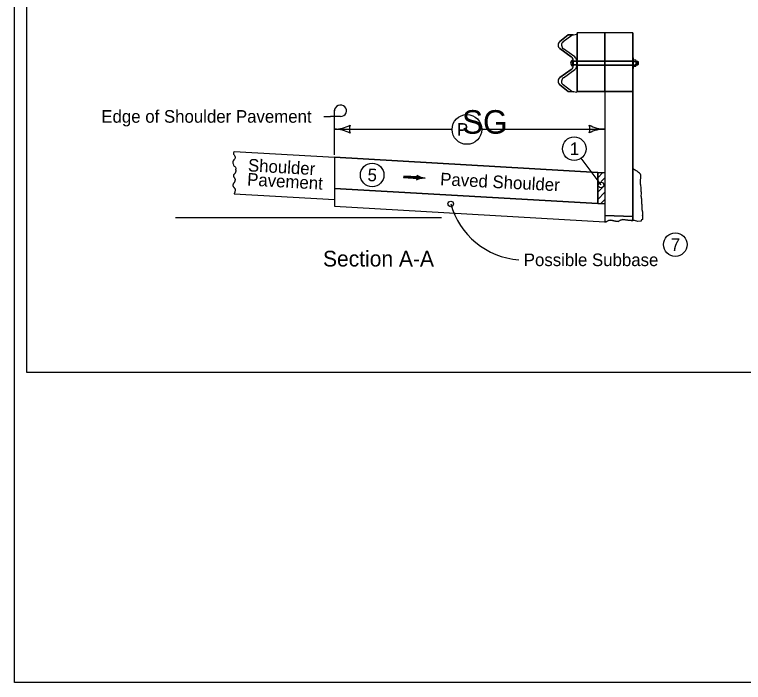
# Model space of a CAD drawing. Extents: x 9538 to 81668, y 7600 to 11751.
# Drawn here: x 17333 to 18260, y 7924 to 8774 of the extents above; entities that cross this region are included whole.
import ezdxf

# ---------------------------------------------------------------- set-up
doc = ezdxf.new("R2010")
doc.units = 0
for name, color, linetype in [('Default', 7, 'Continuous'), ('DsnShtMinorGrid13', 7, 'Continuous'), ('DsnShtMinorGrid14', 7, 'Continuous'), ('dsnStdCells', 7, 'Continuous'), ('dsnStdDimension', 7, 'Continuous'), ('dsnStdNameDate', 7, 'Continuous'), ('dsnStdNote', 7, 'Continuous'), ('dsnStdShading', 7, 'Continuous'), ('dsnStdTable', 7, 'Continuous')]:
    doc.layers.add(name, color=color, linetype=linetype)

msp = doc.modelspace()

# ---------------------------------------------------------------- linework, layer by layer
at = {"layer": 'Default'}
msp.add_lwpolyline([(17332.53, 9944.02), (20467.54, 9944.02), (20467.54, 7924.02), (17332.53, 7924.02)], close=True, dxfattribs=at)
at = {"layer": 'DsnShtMinorGrid13'}
for centre, radius in [((18044.8, 8603.28), 15), ((17787.59, 8569.91), 15), ((18078.92, 8557.17), 3.58), ((18173.39, 8481.26), 15)]:
    msp.add_circle(centre, radius, dxfattribs=at)
at = {"layer": 'DsnShtMinorGrid14'}
msp.add_circle((17887.63, 8533.07), 3.54, dxfattribs=at)
at = {"layer": 'dsnStdCells'}
for p, q in [((18026.57, 8730.73), (18041.08, 8720.31)), ((18041.08, 8704.24), (18026.57, 8693.82))]:
    msp.add_line(p, q, dxfattribs=at)
for points in [[(18030.82, 8739.63), (18030.8, 8739.62), (18041.58, 8748.02), (18043.47, 8748.36), (18037.14, 8748.24), (18026.37, 8739.85)], [(18083.86, 8714.93), (18083.86, 8750.61), (18048.31, 8750.61), (18048.31, 8714.93), (18048.31, 8714.93), (18083.86, 8714.93)], [(18119.41, 8714.93), (18119.41, 8718.93), (18119.41, 8750.61), (18083.86, 8750.61), (18083.86, 8714.93), (18119.41, 8714.93)], [(18045.52, 8720.09), (18045.55, 8720.07), (18030.98, 8730.53), (18031.01, 8730.51)], [(18043.47, 8715.68), (18043.47, 8714.6), (18047.92, 8714.6), (18047.92, 8715.46), (18047.92, 8715.46)], [(18047.92, 8708.65), (18047.92, 8708.65), (18047.92, 8709.93), (18043.47, 8709.93), (18043.47, 8708.87), (18043.47, 8709.93), (18043.47, 8709.93), (18043.47, 8708.87)], [(18048.31, 8714.6), (18048.31, 8709.93), (18048.32, 8709.93), (18083.86, 8709.93), (18083.86, 8714.6), (18048.31, 8714.6), (18048.31, 8714.6)], [(18119.41, 8709.93), (18119.41, 8714.6), (18083.86, 8714.6), (18083.86, 8709.93), (18119.41, 8709.93)], [(18031.01, 8693.6), (18030.98, 8693.58), (18045.55, 8704.04), (18045.52, 8704.02)], [(18048.31, 8709.6), (18048.31, 8675.96), (18083.86, 8675.96), (18083.86, 8709.6), (18048.31, 8709.6)], [(18119.41, 8675.96), (18119.41, 8705.6), (18119.41, 8709.6), (18083.86, 8709.6), (18083.86, 8675.96), (18119.41, 8675.96)], [(18026.37, 8684.7), (18037.14, 8676.31), (18044.24, 8675.62), (18041.58, 8676.09), (18030.8, 8684.5), (18030.82, 8684.48)], [(18119.41, 8517.01), (18119.41, 8675.96), (18083.86, 8675.96), (18083.86, 8572.99), (18083.86, 8566.3), (18083.86, 8566.3), (18083.86, 8566.3), (18083.86, 8557.07), (18083.86, 8557.07), (18083.86, 8557.07), (18083.86, 8547.93), (18083.86, 8547.93), (18083.86, 8547.93), (18083.86, 8541), (18083.86, 8518.17), (18119.41, 8517.01)], [(18119.41, 8517.01), (18083.86, 8518.17), (18083.86, 8510.15), (18085.5, 8510.38), (18088.25, 8511.97), (18091.54, 8512.5), (18097.16, 8510.91), (18100.87, 8510.69), (18103.52, 8512.5), (18106.59, 8513.13), (18112.84, 8512.39), (18117.08, 8511.97), (18119.41, 8511.97), (18119.41, 8517.01)]]:
    msp.add_lwpolyline(points, dxfattribs=at)
msp.add_lwpolyline([(18047.92, 8714.6), (18043.47, 8714.6), (18043.47, 8711.14), (18043.47, 8712.27), (18043.47, 8709.93), (18047.92, 8709.93)], close=True, dxfattribs=at)
for centre, start, end in [((18029.85, 8735.36), 127.75002, 234.69086), ((18034.29, 8735.14), 127.75002, 234.69086), ((18037.8, 8715.68), 0, 54.69099), ((18042.24, 8715.46), 0, 54.69099), ((18037.8, 8708.87), 305.30901, 0), ((18042.24, 8708.65), 305.30901, 0), ((18029.85, 8689.19), 125.30914, 232.24998), ((18034.29, 8688.97), 125.30914, 232.24998)]:
    msp.add_arc(centre, 5.68, start, end, dxfattribs=at)
at = {"layer": 'dsnStdDimension'}
for p, q in [((17739.47, 8628.24), (17889.3, 8628.24)), ((17927.15, 8628.4), (18083.86, 8628.4))]:
    msp.add_line(p, q, dxfattribs=at)
msp.add_circle((17908.23, 8627.84), 18.93, dxfattribs=at)
for centre, radius, start, end in [((17739.47, 8670.74), 42.5, 270, 298.07249), ((17739.47, 8585.74), 42.5, 61.92751, 90), ((17775.11, 8628.24), 16.42, 162.26665, 197.73335), ((18048.22, 8628.4), 16.42, 342.26665, 17.73335), ((18083.86, 8670.9), 42.5, 241.92751, 270), ((18083.86, 8585.9), 42.5, 90, 118.07249), ((17981.79, 8559.36), 97.76, 195.59781, 265.55799)]:
    msp.add_arc(centre, radius, start, end, dxfattribs=at)
at = {"layer": 'dsnStdNameDate'}
msp.add_line((18078.92, 8557.17), (18053.54, 8591.09), dxfattribs=at)
at = {"layer": 'dsnStdNote'}
for p, q in [((17739.47, 8631.56), (17739.47, 8652.42)), ((17726.1, 8644.41), (17734.78, 8644.41)), ((17747.28, 8644.41), (17734.78, 8644.41)), ((17739.47, 8595.62), (17739.47, 8631.56)), ((17845.85, 8566.52), (17827.65, 8567.57)), ((17845.75, 8565.58), (17845.75, 8565.58)), ((17845.87, 8567.53), (17845.87, 8567.53))]:
    msp.add_line(p, q, dxfattribs=at)
for points in [[(17845.88, 8567.46), (17827.71, 8568.51), (17827.58, 8566.63), (17845.75, 8565.58), (17845.8, 8567.19), (17827.93, 8568.29), (17827.88, 8566.79), (17845.37, 8565.84), (17845.49, 8566.96), (17828.17, 8568.02), (17828.14, 8567.02), (17845.15, 8566.04), (17845.25, 8566.75), (17828.36, 8567.8), (17828.34, 8567.24), (17844.94, 8566.31)], [(17845.48, 8568.72), (17846.17, 8567.55), (17846.15, 8565.9), (17845.39, 8564.51), (17848.14, 8565.37), (17851.34, 8566.02), (17852.24, 8566.16), (17849.99, 8566.7), (17846.77, 8567.93), (17845.82, 8568.47), (17845.95, 8564.95), (17850.89, 8566.17), (17846.25, 8567.75), (17846.27, 8565.33), (17849.67, 8566.26), (17846.67, 8567.12), (17846.43, 8565.74), (17848.59, 8566.24), (17847.01, 8566.75), (17846.87, 8566.09), (17847.66, 8566.25)]]:
    msp.add_lwpolyline(points, dxfattribs=at)
for centre, major_axis, start_param, end_param in [((17747.28, 8651.54), (-7.81, 0), 1.570796, 6.283185), ((17842.08, 8566.74), (3.88, 0), 5.202895, 7.237436), ((17854.36, 8545.74), (22.17, 0), 1.537172, 2.061295), ((17857.15, 8586.16), (-22.17, 0), 0.954258, 1.478381)]:
    msp.add_ellipse(centre, major_axis=major_axis, ratio=0.913811, start_param=start_param, end_param=end_param, dxfattribs=at)
at = {"layer": 'dsnStdShading'}
for p, q in [((17347.53, 9929.02), (17347.53, 8319.02)), ((17347.53, 8319.02), (20443.23, 8319.02))]:
    msp.add_line(p, q, dxfattribs=at)
at = {"layer": 'dsnStdTable'}
for p, q in [((18026.37, 8739.85), (18037.14, 8748.24)), ((18030.8, 8739.62), (18041.58, 8748.02)), ((18037.14, 8748.24), (18043.47, 8748.36)), ((18041.58, 8748.02), (18047.92, 8749.14)), ((18119.41, 8750.61), (18048.31, 8750.61)), ((18048.31, 8675.96), (18048.31, 8750.61)), ((18083.86, 8675.96), (18083.86, 8750.61)), ((18119.41, 8750.61), (18119.41, 8511.97)), ((18041.08, 8720.31), (18026.57, 8730.73)), ((18045.55, 8720.07), (18030.98, 8730.53)), ((18042.7, 8708.21), (18042.7, 8716.29)), ((18042.7, 8714.6), (18048.13, 8714.6)), ((18042.7, 8709.93), (18048.31, 8709.93)), ((18043.47, 8708.87), (18043.47, 8715.68)), ((18043.47, 8708.87), (18043.47, 8712.27)), ((18043.47, 8712.27), (18043.47, 8708.87)), ((18043.64, 8714.6), (18048.31, 8714.6)), ((18047.92, 8712.06), (18047.92, 8715.46)), ((18047.92, 8708.65), (18047.92, 8712.06)), ((18047.92, 8712.06), (18047.92, 8708.65)), ((18048.31, 8714.93), (18119.41, 8714.93)), ((18048.31, 8714.6), (18119.41, 8714.6)), ((18048.32, 8709.93), (18119.41, 8709.93)), ((18119.41, 8718.9), (18120.09, 8718.9)), ((18120.09, 8705.57), (18120.09, 8718.9)), ((18120.09, 8716.28), (18123.05, 8716.28)), ((18120.09, 8714.26), (18123.05, 8714.26)), ((18120.09, 8710.22), (18123.05, 8710.22)), ((18123.42, 8709.21), (18123.42, 8715.27)), ((18123.42, 8714.57), (18125.79, 8714.57)), ((18123.42, 8709.9), (18125.79, 8709.9)), ((18124.31, 8714.57), (18124.31, 8709.9)), ((18125.05, 8714.57), (18125.05, 8709.9)), ((18125.79, 8714.57), (18126.24, 8714.04)), ((18125.79, 8714.57), (18125.79, 8709.9)), ((18126.24, 8710.44), (18125.79, 8709.9)), ((18126.24, 8714.04), (18126.24, 8710.44)), ((18026.57, 8693.82), (18041.08, 8704.24)), ((18030.98, 8693.58), (18045.55, 8704.04)), ((18048.31, 8709.6), (18119.41, 8709.6)), ((18119.41, 8705.57), (18120.09, 8705.57)), ((18120.09, 8708.2), (18123.05, 8708.2)), ((18037.14, 8676.31), (18026.37, 8684.7)), ((18041.58, 8676.09), (18030.8, 8684.5)), ((18044.24, 8675.62), (18037.14, 8676.31)), ((18047.92, 8674.97), (18041.58, 8676.09)), ((18083.86, 8675.96), (18048.31, 8675.96)), ((18083.86, 8675.96), (18083.86, 8509.43)), ((17611.85, 8599.9), (17739.47, 8592.48)), ((17739.47, 8592.48), (17739.47, 8538.47)), ((17739.47, 8592.48), (18074.61, 8572.99)), ((18074.61, 8572.99), (17739.47, 8592.48)), ((17739.47, 8592.48), (17739.47, 8552.88)), ((18074.61, 8566.25), (18081.35, 8572.99)), ((18074.61, 8566.25), (18081.35, 8572.99)), ((18074.61, 8566.25), (18081.35, 8572.99)), ((18074.61, 8566.25), (18081.35, 8572.99)), ((18074.61, 8572.99), (18083.84, 8572.99)), ((18074.61, 8572.99), (18074.61, 8533.56)), ((18074.61, 8533.56), (18074.61, 8572.99)), ((18074.61, 8557.06), (18083.84, 8566.3)), ((18074.61, 8557.06), (18083.84, 8566.3)), ((18074.61, 8557.06), (18083.84, 8566.3)), ((18074.61, 8557.06), (18083.84, 8566.3)), ((18129.45, 8566.23), (18129.45, 8566.23)), ((18074.61, 8533.56), (17739.47, 8552.88)), ((17739.47, 8552.88), (18074.61, 8533.56)), ((18074.61, 8547.84), (18083.84, 8557.07)), ((18074.61, 8547.84), (18083.84, 8557.07)), ((18074.61, 8547.84), (18083.84, 8557.07)), ((18074.61, 8547.84), (18083.84, 8557.07)), ((17612.04, 8545.88), (17739.47, 8538.47)), ((18074.61, 8538.61), (18083.84, 8547.84)), ((17739.47, 8538.47), (17739.47, 8530.05)), ((18074.61, 8533.56), (18083.84, 8533.56)), ((18078.7, 8533.56), (18083.84, 8538.7)), ((17739.47, 8530.05), (18083.86, 8510.19)), ((17537.41, 8515.64), (17875.92, 8515.64))]:
    msp.add_line(p, q, dxfattribs=at)
for points in [[(18123.4, 8709.53), (18123.36, 8709.8), (18123.31, 8709.97), (18123.22, 8710.13), (18123.11, 8710.22), (18123.18, 8710.32), (18123.27, 8710.54), (18123.33, 8710.85), (18123.41, 8711.6), (18123.4, 8709.53), (18123.39, 8709.67), (18123.34, 8709.88), (18123.27, 8710.09), (18123.15, 8710.21), (18123.19, 8710.29), (18123.25, 8710.44), (18123.35, 8710.94), (18123.39, 8711.32), (18123.39, 8709.72), (18123.36, 8709.84), (18123.31, 8710), (18123.18, 8710.21), (18123.24, 8710.38), (18123.32, 8710.71), (18123.37, 8711.04), (18123.36, 8709.87), (18123.32, 8710), (18123.21, 8710.2), (18123.26, 8710.41), (18123.31, 8710.67), (18123.35, 8710.84), (18123.35, 8709.98), (18123.29, 8710.09), (18123.24, 8710.2), (18123.33, 8710.66), (18123.32, 8710.06), (18123.26, 8710.2), (18123.31, 8710.49), (18123.31, 8710.14), (18123.27, 8710.21), (18123.29, 8710.31), (18123.29, 8710.23)], [(18123.12, 8714.26), (18123.19, 8714.3), (18123.26, 8714.41), (18123.35, 8714.63), (18123.4, 8714.91), (18123.41, 8712.97), (18123.35, 8713.48), (18123.29, 8713.85), (18123.18, 8714.17), (18123.12, 8714.26), (18123.17, 8714.27), (18123.28, 8714.41), (18123.36, 8714.64), (18123.39, 8714.79), (18123.39, 8713.26), (18123.32, 8713.75), (18123.26, 8714.01), (18123.15, 8714.24), (18123.19, 8714.25), (18123.32, 8714.47), (18123.36, 8714.62), (18123.37, 8713.51), (18123.18, 8714.23), (18123.35, 8714.5), (18123.35, 8713.65), (18123.2, 8714.21), (18123.33, 8714.43), (18123.33, 8713.79), (18123.22, 8714.2), (18123.31, 8714.37), (18123.31, 8713.96), (18123.24, 8714.18), (18123.29, 8714.3), (18123.3, 8714.09), (18123.27, 8714.17), (18123.28, 8714.21)], [(18129.93, 8542.38), (18129.87, 8542.11), (18129.87, 8541.92), (18129.87, 8541.72), (18129.87, 8541.53), (18129.87, 8541.33), (18129.87, 8541.14), (18129.87, 8540.84), (18129.87, 8540.65), (18129.97, 8540.35), (18130.06, 8540.06), (18130.26, 8539.87), (18130.26, 8539.67), (18130.36, 8539.47), (18130.36, 8539.28), (18130.36, 8539.08), (18130.45, 8538.99), (18130.45, 8538.79), (18130.45, 8538.59), (18130.45, 8538.4), (18130.45, 8538.2), (18130.45, 8538.01), (18130.45, 8537.72), (18130.45, 8537.42), (18130.45, 8537.23), (18130.45, 8536.93), (18130.45, 8536.74), (18130.45, 8536.54), (18130.55, 8536.45), (18130.55, 8536.25), (18130.55, 8536.05), (18130.55, 8535.86), (18130.55, 8535.66), (18130.55, 8535.47), (18130.55, 8535.27), (18130.55, 8535.08), (18130.55, 8534.88), (18130.55, 8534.69), (18130.55, 8534.49), (18130.55, 8534.3), (18130.55, 8534.1), (18130.55, 8533.91), (18130.55, 8533.71), (18130.55, 8533.51), (18130.55, 8533.32), (18130.55, 8533.12), (18130.55, 8532.93), (18130.65, 8532.83), (18130.65, 8532.63), (18130.65, 8532.44), (18130.75, 8532.34), (18130.75, 8532.15), (18130.75, 8531.95), (18130.85, 8531.85), (18130.85, 8531.66), (18130.85, 8531.46), (18130.85, 8531.27), (18130.85, 8530.97), (18130.94, 8530.68), (18130.94, 8530.49), (18130.94, 8530.29), (18130.94, 8530.09), (18130.94, 8529.9), (18130.94, 8529.7), (18130.94, 8529.51), (18130.94, 8529.31), (18130.94, 8529.12), (18130.94, 8528.92), (18130.94, 8528.73), (18130.94, 8528.53), (18130.94, 8528.34), (18130.94, 8528.14), (18130.94, 8527.95), (18130.94, 8527.75), (18130.94, 8527.55), (18130.94, 8527.36), (18130.94, 8527.16), (18130.94, 8526.97), (18130.94, 8526.77), (18130.94, 8526.58), (18130.94, 8526.38), (18130.94, 8526.19), (18130.94, 8525.99), (18130.94, 8525.8), (18130.94, 8525.6), (18130.94, 8525.4), (18130.94, 8525.21), (18130.94, 8525.01), (18131.04, 8524.92), (18131.04, 8524.62), (18131.04, 8524.43), (18131.14, 8524.23), (18131.24, 8523.94), (18131.24, 8523.74), (18131.33, 8523.65), (18131.33, 8523.45), (18131.43, 8523.35), (18131.53, 8523.26), (18131.53, 8523.06), (18131.53, 8522.86), (18131.53, 8522.67), (18131.63, 8522.57), (18131.63, 8522.38), (18131.63, 8522.18), (18131.63, 8521.99), (18131.63, 8521.79), (18131.63, 8521.59), (18131.63, 8521.4), (18131.63, 8521.2), (18131.63, 8521.01), (18131.63, 8520.81), (18131.63, 8520.62), (18131.63, 8520.42), (18131.63, 8520.23), (18131.63, 8520.03), (18131.63, 8519.84), (18131.63, 8519.64), (18131.63, 8519.44), (18131.63, 8519.25), (18131.63, 8519.05), (18131.63, 8518.86), (18131.63, 8518.66), (18131.63, 8518.47), (18131.63, 8518.27), (18131.63, 8518.08), (18131.63, 8517.88), (18131.63, 8517.69), (18131.63, 8517.69), (18131.63, 8517.98), (18131.63, 8518.17), (18131.63, 8518.37), (18131.63, 8518.17), (18131.63, 8517.98), (18131.63, 8517.78), (18131.63, 8517.59), (18131.63, 8517.39), (18131.63, 8517.2), (18131.63, 8517), (18131.63, 8516.81), (18131.63, 8516.61), (18131.63, 8516.42), (18131.63, 8516.22), (18131.63, 8516.03), (18131.63, 8515.83), (18131.63, 8515.63), (18131.63, 8515.44), (18131.53, 8515.34), (18131.53, 8515.15), (18131.53, 8514.95), (18131.53, 8514.76), (18131.53, 8514.56), (18131.53, 8514.36), (18131.53, 8514.17), (18131.53, 8513.97), (18131.53, 8513.78), (18131.53, 8513.58), (18131.53, 8513.39), (18131.43, 8513.29), (18131.33, 8513.09), (18131.24, 8513), (18131.14, 8512.9), (18131.04, 8512.8), (18130.85, 8512.7), (18130.65, 8512.7), (18130.55, 8512.61), (18130.45, 8512.51), (18130.36, 8512.41), (18130.16, 8512.31), (18130.06, 8512.21), (18130.06, 8512.02), (18129.97, 8511.92), (18129.97, 8511.73), (18129.97, 8511.53), (18129.97, 8511.34), (18129.97, 8511.14), (18129.97, 8511.04), (18129.97, 8511.24)], [(18129.92, 8510.92), (18125.77, 8510.8), (18121.64, 8511.97), (18117.08, 8511.97), (18112.84, 8512.39), (18106.59, 8513.13), (18103.52, 8512.5), (18100.87, 8510.69), (18097.16, 8510.91), (18091.54, 8512.5), (18088.25, 8511.97), (18085.5, 8510.38), (18083.86, 8510.15)]]:
    msp.add_lwpolyline(points, dxfattribs=at)
msp.add_circle((17787.59, 8569.91), 15, dxfattribs=at)
for centre, radius, start, end in [((18029.85, 8735.36), 5.68, 127.75002, 234.69086), ((18034.29, 8735.14), 5.68, 127.75002, 234.69086), ((18037.8, 8715.68), 5.68, 360, 54.69099), ((18042.24, 8715.46), 5.68, 360, 54.69099), ((18044.77, 8712.26), 4.54, 117.20289, 242.8461), ((18037.8, 8708.87), 5.68, 305.30901, 0), ((18042.24, 8708.65), 5.68, 305.30901, 0), ((18029.85, 8689.19), 5.68, 125.30914, 232.24998), ((18034.29, 8688.97), 5.68, 125.30914, 232.24998)]:
    msp.add_arc(centre, radius, start, end, dxfattribs=at)
for centre in [(18123.05, 8715.27), (18123.05, 8709.21)]:
    msp.add_ellipse(centre, major_axis=(0, -1.01), ratio=0.362258, start_param=6.283156, end_param=9.424748, dxfattribs=at)
for points in [[(17611.85, 8599.9), (17611.35, 8596.3), (17612.39, 8594.79), (17613.26, 8592.5), (17612.65, 8590.44), (17610.74, 8588.06), (17610.22, 8586.16), (17610.74, 8583.87), (17611.61, 8581.49), (17612.65, 8580.78), (17614.04, 8578.24), (17614.03, 8577.4)], [(17612.06, 8560.29), (17612.28, 8560.54), (17612.47, 8560.8), (17612.83, 8561.36), (17613.11, 8561.95), (17613.22, 8562.26), (17613.32, 8562.57), (17613.46, 8563.19), (17613.5, 8563.81), (17613.46, 8564.4), (17613.4, 8564.68), (17613.36, 8564.81), (17613.32, 8564.94), (17613.11, 8565.32), (17612.82, 8565.68), (17612.52, 8566.05), (17612.28, 8566.45), (17612.14, 8566.73), (17612, 8567.01), (17611.74, 8567.59), (17611.53, 8568.15), (17611.46, 8568.45), (17611.41, 8568.74), (17611.4, 8568.87), (17611.4, 8569), (17611.55, 8569.77), (17611.76, 8570.29), (17612.02, 8570.8), (17612.46, 8571.44), (17612.98, 8571.98), (17613.49, 8572.53), (17613.72, 8572.84), (17613.92, 8573.18), (17614.13, 8573.65), (17614.28, 8574.13), (17614.39, 8574.6), (17614.42, 8574.84), (17614.43, 8574.96), (17614.44, 8575.08), (17614.39, 8575.59), (17614.24, 8576.1), (17614.19, 8576.23), (17614.14, 8576.35), (17614.09, 8576.48), (17614.07, 8576.61), (17614.03, 8577.4)], [(18129.93, 8542.38), (18130.25, 8545.29), (18130.03, 8550.15), (18129.58, 8555.9), (18128.92, 8560.33), (18129.14, 8563.64), (18129.58, 8567.84), (18128.92, 8570.94), (18126.71, 8572.93), (18124.72, 8574.7), (18122.51, 8575.81), (18120.3, 8577.13), (18119.41, 8577.8)], [(17612.06, 8560.29), (17611.85, 8560.06), (17611.6, 8559.82), (17611.37, 8559.58), (17611.19, 8559.31), (17611.04, 8559.03), (17610.91, 8558.74), (17610.65, 8558.17), (17610.53, 8557.89), (17610.44, 8557.6), (17610.37, 8557.31), (17610.34, 8557.16), (17610.32, 8557.01), (17610.33, 8556.5), (17610.46, 8555.98), (17610.67, 8555.46), (17610.93, 8554.95), (17611.37, 8554.32), (17611.89, 8553.77), (17612.4, 8553.22), (17612.63, 8552.92), (17612.83, 8552.58), (17613.23, 8551.63), (17613.34, 8551.16), (17613.35, 8550.68), (17613.32, 8550.39), (17613.27, 8550.1), (17613.21, 8549.81), (17613.15, 8549.53), (17612.83, 8548.38), (17612.65, 8547.77), (17612.46, 8547.17), (17612.23, 8546.58), (17612.11, 8546.29), (17611.97, 8546.01), (17611.88, 8545.89)]]:
    msp.add_spline(points, degree=3, dxfattribs=at)

# ---------------------------------------------------------------- texts
at = {"layer": 'DsnShtMinorGrid13'}
for s, p in [('1', (18039.18, 8595.28)), ('7', (18167.68, 8473.26))]:
    msp.add_text(s, height=16, dxfattribs=at).set_placement(p)
msp.add_text('5', height=16, rotation=356.69973, dxfattribs=at).set_placement((17781.37, 8562.26))
at = {"layer": 'dsnStdDimension'}
for s, height, p in [('SG', 30, (17901.94, 8622.4)), ('P', 16, (17895.51, 8619.84))]:
    msp.add_text(s, height=height, dxfattribs=at).set_placement(p)
at = {"layer": 'dsnStdNote'}
for s, height, p in [('Edge of Shoulder Pavement', 16, (17442.94, 8636.41)), ('Section A-A', 20, (17725.04, 8453.39)), ('Possible Subbase', 16, (17980.57, 8453.89))]:
    msp.add_text(s, height=height, dxfattribs=at).set_placement(p)
for s, rotation, p in [('Shoulder', 356.73462, (17629.23, 8574.55)), ('Pavement', 356.73462, (17628.2, 8556.58)), ('Paved Shoulder ', 357.0678, (17873.87, 8556.89))]:
    msp.add_text(s, height=16, rotation=rotation, dxfattribs=at).set_placement(p)

doc.saveas('drawing.dxf')
